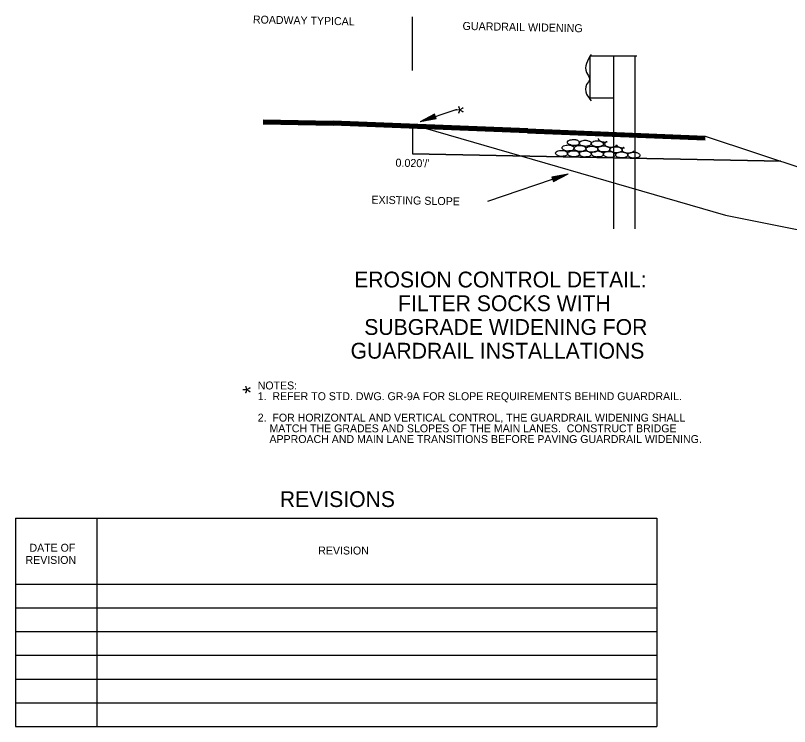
# Model space of a CAD drawing. Extents: x 1929624 to 1932070, y 596315 to 605533.
# Drawn here: x 1930529 to 1931116, y 604566 to 605106 of the extents above; entities that cross this region are included whole.
import ezdxf

# ---------------------------------------------------------------- set-up
doc = ezdxf.new("R2010")
doc.units = 0
for name, color, linetype in [('Default', 7, 'Continuous'), ('R_Border', 7, 'Continuous'), ('R_Logo', 7, 'Continuous')]:
    doc.layers.add(name, color=color, linetype=linetype)

msp = doc.modelspace()

# ---------------------------------------------------------------- linework, layer by layer
at = {"layer": 'Default'}
for p, q in [((1930964.98, 605075.01), (1930964.98, 605043.17)), ((1930964.98, 605075.01), (1931000.63, 605075.01)), ((1930982.82, 605075.01), (1930982.82, 604943.82)), ((1930999.21, 605074.86), (1930999.21, 604943.7)), ((1930964.98, 605043.17), (1930982.82, 605043.17)), ((1930863.17, 605034.12), (1930836.07, 605024.93)), ((1930847.11, 605030.72), (1930836.07, 605024.93)), ((1930848.31, 605027.26), (1930836.07, 605024.93)), ((1930847.23, 605030.43), (1930838, 605025.58)), ((1930848.23, 605027.52), (1930838, 605025.58)), ((1930847.34, 605030.1), (1930840.07, 605026.32)), ((1930848.09, 605027.84), (1930840.07, 605026.32)), ((1930847.39, 605029.82), (1930841.99, 605026.99)), ((1930847.99, 605028.14), (1930841.99, 605026.99)), ((1930847.51, 605029.56), (1930843.92, 605027.67)), ((1930847.88, 605028.46), (1930843.92, 605027.67)), ((1930847.61, 605029.26), (1930845.88, 605028.36)), ((1930847.83, 605028.76), (1930845.88, 605028.36)), ((1930848.31, 605027.26), (1930847.11, 605030.72)), ((1930717.07, 605026.44), (1930770.24, 605025.38)), ((1930717.07, 605025.7), (1930770.24, 605024.64)), ((1930717.1, 605024.96), (1930770.24, 605023.91)), ((1930717.12, 605024.23), (1930770.24, 605023.17)), ((1930717.15, 605023.49), (1930770.19, 605022.43)), ((1930717.15, 605023.39), (1930770.24, 605022.33)), ((1930917.77, 605016.53), (1930770.14, 605022.43)), ((1930917.82, 605018), (1930770.19, 605023.91)), ((1930917.82, 605017.26), (1930770.19, 605023.17)), ((1930917.87, 605019.48), (1930770.24, 605025.38)), ((1930917.87, 605018.74), (1930770.24, 605024.64)), ((1930917.77, 605016.43), (1930770.24, 605022.33)), ((1930830.34, 605022.98), (1930830.34, 605000.56)), ((1930917.74, 605016.53), (1931052.4, 605011.14)), ((1930917.77, 605017.26), (1931052.42, 605011.87)), ((1930917.8, 605018), (1931052.46, 605012.61)), ((1930917.82, 605018.74), (1931052.48, 605013.35)), ((1930917.87, 605019.48), (1931052.52, 605014.09)), ((1931052.52, 605014.09), (1931287.53, 604935.97)), ((1930887.54, 604964.72), (1930948.45, 604985.4)), ((1930936.22, 604983.06), (1930948.45, 604985.4)), ((1930936.22, 604983.06), (1930937.42, 604979.61)), ((1930936.3, 604982.8), (1930946.52, 604984.74)), ((1930936.44, 604982.48), (1930944.45, 604984)), ((1930936.53, 604982.18), (1930942.54, 604983.33)), ((1930936.65, 604981.87), (1930940.61, 604982.65)), ((1930936.69, 604981.57), (1930938.64, 604981.96)), ((1930936.92, 604981.07), (1930938.64, 604981.96)), ((1930937.01, 604980.76), (1930940.61, 604982.65)), ((1930937.14, 604980.5), (1930942.54, 604983.33)), ((1930937.19, 604980.23), (1930944.45, 604984)), ((1930937.29, 604979.89), (1930946.52, 604984.74)), ((1930937.42, 604979.61), (1930948.45, 604985.4))]:
    msp.add_line(p, q, dxfattribs=at)
for points in [[(1930965.84, 605076.04), (1930962.5, 605069.13), (1930962.32, 605062.39), (1930964.74, 605057.2), (1930962.5, 605053.26), (1930962.5, 605046), (1930966.04, 605040.76)], [(1930952.73, 605011.46), (1930951.11, 605011.37), (1930949.14, 605010.78), (1930948.1, 605009.84), (1930947.96, 605009.3), (1930948.45, 605008.32), (1930949.04, 605007.87), (1930950.17, 605007.33), (1930951.74, 605006.89), (1930952.58, 605006.89), (1930953.76, 605006.99), (1930955.09, 605007.13), (1930956.12, 605007.53), (1930957.01, 605008.36), (1930957.16, 605009), (1930956.86, 605009.89), (1930956.22, 605010.48), (1930955.53, 605010.87), (1930954.45, 605011.32), (1930953.76, 605011.46), (1930952.73, 605011.46)], [(1930961.55, 605010.94), (1930959.92, 605010.84), (1930958, 605010.15), (1930957.02, 605009.37), (1930956.87, 605008.82), (1930957.41, 605007.79), (1930957.85, 605007.25), (1930959.04, 605006.76), (1930960.51, 605006.41), (1930961.35, 605006.31), (1930962.58, 605006.36), (1930963.96, 605006.61), (1930964.94, 605007.05), (1930965.97, 605007.84), (1930966.12, 605008.48), (1930965.83, 605009.37), (1930965.09, 605010.01), (1930964.35, 605010.35), (1930963.27, 605010.69), (1930962.58, 605010.84), (1930961.55, 605010.94)], [(1930970.72, 605010.57), (1930969.1, 605010.52), (1930967.13, 605009.83), (1930966.15, 605008.95), (1930966, 605008.36), (1930966.54, 605007.37), (1930967.08, 605006.93), (1930968.16, 605006.44), (1930969.74, 605005.99), (1930970.58, 605005.95), (1930971.76, 605006.04), (1930973.08, 605006.29), (1930974.12, 605006.68), (1930975.1, 605007.47), (1930975.25, 605008.06), (1930974.95, 605008.95), (1930974.22, 605009.54), (1930973.53, 605010.03), (1930972.44, 605010.37), (1930971.76, 605010.52), (1930970.72, 605010.57)], [(1930971.34, 605012.16), (1930971.34, 605012.13), (1930971.34, 605012.06), (1930971.35, 605012), (1930971.42, 605011.73), (1930971.54, 605011.47), (1930971.69, 605011.21), (1930971.79, 605011.09), (1930971.89, 605010.96), (1930972.14, 605010.72), (1930972.43, 605010.52), (1930972.69, 605010.38), (1930972.96, 605010.25), (1930973.23, 605010.13), (1930973.51, 605010.03), (1930974.29, 605009.81), (1930975.09, 605009.64), (1930975.5, 605009.57), (1930975.71, 605009.55), (1930975.92, 605009.54), (1930976.51, 605009.57), (1930976.81, 605009.6), (1930977.1, 605009.64), (1930977.63, 605009.72), (1930978.14, 605009.82)], [(1930978, 605009.87), (1930977.7, 605009.75), (1930977.46, 605009.64), (1930977.22, 605009.51), (1930976.93, 605009.33), (1930976.67, 605009.12), (1930976.45, 605008.87), (1930976.34, 605008.73), (1930976.24, 605008.58), (1930976.16, 605008.44), (1930976.11, 605008.31), (1930976.08, 605008.17), (1930976.08, 605008.1), (1930976.09, 605008.04), (1930976.16, 605007.77), (1930976.28, 605007.5), (1930976.44, 605007.25), (1930976.53, 605007.12), (1930976.63, 605007), (1930976.89, 605006.75), (1930977.17, 605006.56), (1930977.44, 605006.42), (1930977.7, 605006.28), (1930977.97, 605006.17), (1930978.25, 605006.07), (1930979.03, 605005.85), (1930979.83, 605005.67), (1930980.66, 605005.58), (1930980.81, 605005.58), (1930980.96, 605005.58), (1930981.26, 605005.6), (1930981.85, 605005.67), (1930982.18, 605005.72), (1930982.51, 605005.78), (1930982.84, 605005.85), (1930983.17, 605005.92), (1930983.44, 605005.99), (1930983.7, 605006.09), (1930983.95, 605006.19), (1930984.21, 605006.31), (1930984.49, 605006.46), (1930984.74, 605006.63), (1930984.98, 605006.84), (1930985.09, 605006.96), (1930985.19, 605007.1), (1930985.26, 605007.22), (1930985.31, 605007.34)], [(1930943.63, 605003.26), (1930942.01, 605003.21), (1930940.04, 605002.53), (1930939.11, 605001.64), (1930938.96, 605001.05), (1930939.45, 605000.07), (1930940.04, 604999.62), (1930941.08, 604999.13), (1930942.7, 604998.69), (1930943.49, 604998.64), (1930944.72, 604998.74), (1930946.05, 604998.98), (1930947.08, 604999.38), (1930948.01, 605000.16), (1930948.16, 605000.75), (1930947.87, 605001.64), (1930947.13, 605002.23), (1930946.44, 605002.72), (1930945.36, 605003.07), (1930944.67, 605003.21), (1930943.63, 605003.26)], [(1930948.65, 605007.36), (1930946.93, 605007.16), (1930945.01, 605006.67), (1930944.03, 605005.73), (1930943.88, 605005.19), (1930944.37, 605004.16), (1930944.96, 605003.71), (1930946.05, 605003.12), (1930947.62, 605002.73), (1930948.41, 605002.73), (1930949.64, 605002.83), (1930951.02, 605002.93), (1930952.05, 605003.42), (1930952.93, 605004.26), (1930953.08, 605004.9), (1930952.79, 605005.78), (1930952.05, 605006.37), (1930951.36, 605006.67), (1930950.28, 605007.11), (1930949.64, 605007.31), (1930948.65, 605007.36)], [(1930957.58, 605006.94), (1930955.96, 605006.89), (1930953.99, 605006.25), (1930953.01, 605005.31), (1930952.86, 605004.77), (1930953.4, 605003.74), (1930953.94, 605003.3), (1930955.03, 605002.8), (1930956.6, 605002.41), (1930957.44, 605002.31), (1930958.62, 605002.41), (1930959.95, 605002.66), (1930960.98, 605003.05), (1930961.96, 605003.84), (1930962.11, 605004.48), (1930961.82, 605005.36), (1930961.08, 605005.95), (1930960.39, 605006.4), (1930959.31, 605006.74), (1930958.62, 605006.89), (1930957.58, 605006.94)], [(1930966.68, 605006.44), (1930965.06, 605006.29), (1930963.09, 605005.75), (1930962.05, 605004.81), (1930961.91, 605004.27), (1930962.45, 605003.29), (1930962.99, 605002.85), (1930964.12, 605002.21), (1930965.65, 605001.86), (1930966.48, 605001.86), (1930967.66, 605001.96), (1930969.09, 605002.01), (1930970.07, 605002.5), (1930971.01, 605003.34), (1930971.16, 605003.98), (1930970.86, 605004.86), (1930970.17, 605005.45), (1930969.44, 605005.8), (1930968.4, 605006.14), (1930967.71, 605006.44), (1930966.68, 605006.44)], [(1930975.64, 605006.67), (1930974.01, 605006.47), (1930972.09, 605005.98), (1930971.11, 605005.04), (1930970.96, 605004.5), (1930971.5, 605003.47), (1930972.04, 605003.03), (1930973.13, 605002.44), (1930974.7, 605002.04), (1930975.49, 605002.04), (1930976.72, 605002.14), (1930978.05, 605002.24), (1930979.13, 605002.73), (1930980.06, 605003.57), (1930980.21, 605004.21), (1930979.92, 605005.09), (1930979.18, 605005.68), (1930978.44, 605005.98), (1930977.41, 605006.47), (1930976.67, 605006.62), (1930975.64, 605006.67)], [(1930984.94, 605006.03), (1930983.31, 605005.98), (1930981.34, 605005.34), (1930980.36, 605004.4), (1930980.21, 605003.86), (1930980.75, 605002.83), (1930981.29, 605002.39), (1930982.38, 605001.89), (1930983.95, 605001.5), (1930984.79, 605001.4), (1930985.97, 605001.5), (1930987.3, 605001.75), (1930988.33, 605002.14), (1930989.31, 605002.93), (1930989.46, 605003.57), (1930989.17, 605004.45), (1930988.43, 605005.04), (1930987.74, 605005.49), (1930986.66, 605005.83), (1930985.97, 605005.98), (1930984.94, 605006.03)], [(1930985.26, 605007.36), (1930985.34, 605007.16), (1930985.45, 605006.96), (1930985.58, 605006.76), (1930985.73, 605006.58), (1930985.99, 605006.33), (1930986.27, 605006.13), (1930986.54, 605005.99), (1930986.8, 605005.86), (1930987.07, 605005.74), (1930987.36, 605005.64), (1930988.14, 605005.42), (1930988.93, 605005.25), (1930989.35, 605005.18), (1930989.56, 605005.16), (1930989.77, 605005.15), (1930990.36, 605005.18), (1930990.95, 605005.25), (1930991.25, 605005.29)], [(1930990.83, 605005.44), (1930990.57, 605005.32), (1930990.44, 605005.25), (1930990.31, 605005.18), (1930990.01, 605005), (1930989.76, 605004.78), (1930989.53, 605004.54), (1930989.43, 605004.4), (1930989.32, 605004.25), (1930989.25, 605004.11), (1930989.19, 605003.98), (1930989.17, 605003.84), (1930989.17, 605003.77), (1930989.17, 605003.71), (1930989.25, 605003.44), (1930989.36, 605003.17), (1930989.52, 605002.92), (1930989.61, 605002.79), (1930989.72, 605002.67), (1930989.97, 605002.42), (1930990.26, 605002.23), (1930990.52, 605002.08), (1930990.79, 605001.95), (1930991.06, 605001.84), (1930991.34, 605001.74), (1930992.12, 605001.52), (1930992.91, 605001.34), (1930993.75, 605001.24), (1930993.9, 605001.25), (1930994.05, 605001.25), (1930994.34, 605001.27), (1930994.93, 605001.34), (1930995.27, 605001.39), (1930995.6, 605001.45), (1930995.93, 605001.52), (1930996.26, 605001.59), (1930996.53, 605001.66), (1930996.79, 605001.76), (1930997.04, 605001.86), (1930997.29, 605001.98), (1930997.57, 605002.13), (1930997.83, 605002.3), (1930998.06, 605002.51), (1930998.17, 605002.63), (1930998.23, 605002.7), (1930998.28, 605002.77), (1930998.33, 605002.85)], [(1930952.74, 605002.98), (1930951.11, 605002.83), (1930949.15, 605002.24), (1930948.21, 605001.35), (1930948.06, 605000.76), (1930948.55, 604999.78), (1930949.05, 604999.34), (1930950.18, 604998.84), (1930951.7, 604998.35), (1930952.54, 604998.35), (1930953.77, 604998.45), (1930955.15, 604998.65), (1930956.13, 604998.99), (1930957.12, 604999.88), (1930957.26, 605000.47), (1930956.97, 605001.35), (1930956.23, 605001.94), (1930955.49, 605002.39), (1930954.46, 605002.78), (1930953.77, 605002.93), (1930952.74, 605002.98)], [(1930961.59, 605002.85), (1930959.96, 605002.65), (1930957.99, 605002.11), (1930957.01, 605001.22), (1930956.86, 605000.63), (1930957.4, 604999.65), (1930957.95, 604999.2), (1930959.03, 604998.61), (1930960.55, 604998.22), (1930961.39, 604998.22), (1930962.62, 604998.32), (1930963.95, 604998.42), (1930964.98, 604998.86), (1930965.97, 604999.75), (1930966.11, 605000.34), (1930965.82, 605001.22), (1930965.08, 605001.81), (1930964.34, 605002.16), (1930963.26, 605002.55), (1930962.62, 605002.8), (1930961.59, 605002.85)], [(1930970.85, 605002.85), (1930969.17, 605002.66), (1930967.2, 605002.12), (1930966.22, 605001.23), (1930966.07, 605000.64), (1930966.61, 604999.66), (1930967.16, 604999.21), (1930968.29, 604998.57), (1930969.81, 604998.23), (1930970.6, 604998.23), (1930971.83, 604998.28), (1930973.21, 604998.42), (1930974.24, 604998.87), (1930975.18, 604999.75), (1930975.32, 605000.34), (1930975.03, 605001.23), (1930974.29, 605001.82), (1930973.55, 605002.16), (1930972.52, 605002.51), (1930971.88, 605002.71), (1930970.85, 605002.85)], [(1930979.92, 605002.48), (1930978.19, 605002.29), (1930976.32, 605001.8), (1930975.29, 605000.86), (1930975.14, 605000.32), (1930975.68, 604999.29), (1930976.23, 604998.84), (1930977.36, 604998.25), (1930978.88, 604997.86), (1930979.67, 604997.86), (1930980.9, 604997.96), (1930982.33, 604998.06), (1930983.31, 604998.55), (1930984.25, 604999.38), (1930984.39, 605000.02), (1930984.1, 605000.91), (1930983.36, 605001.5), (1930982.67, 605001.8), (1930981.59, 605002.19), (1930980.95, 605002.44), (1930979.92, 605002.48)], [(1930989.19, 605002.11), (1930987.57, 605002.01), (1930985.65, 605001.32), (1930984.66, 605000.53), (1930984.52, 604999.99), (1930985.06, 604998.96), (1930985.5, 604998.42), (1930986.68, 604997.92), (1930988.16, 604997.58), (1930989, 604997.48), (1930990.23, 604997.53), (1930991.6, 604997.78), (1930992.59, 604998.22), (1930993.62, 604999.01), (1930993.77, 604999.65), (1930993.47, 605000.53), (1930992.73, 605001.17), (1930992, 605001.52), (1930990.91, 605001.86), (1930990.23, 605002.01), (1930989.19, 605002.11)], [(1930998.44, 605001.92), (1930996.82, 605001.77), (1930994.85, 605001.18), (1930993.92, 605000.29), (1930993.77, 604999.7), (1930994.26, 604998.72), (1930994.75, 604998.28), (1930995.88, 604997.79), (1930997.41, 604997.29), (1930998.25, 604997.29), (1930999.48, 604997.39), (1931000.85, 604997.59), (1931001.84, 604997.93), (1931002.82, 604998.82), (1931002.97, 604999.41), (1931002.67, 605000.29), (1931001.94, 605000.89), (1931001.2, 605001.33), (1931000.17, 605001.72), (1930999.48, 605001.87), (1930998.44, 605001.92)]]:
    msp.add_spline(points, degree=3, dxfattribs=at)
at = {"layer": 'R_Border'}
for p, q in [((1930830.34, 605063.76), (1930830.34, 605104.53)), ((1930830.3, 605000.56), (1931109.97, 604995)), ((1931109.97, 604995), (1930830.3, 605000.56)), ((1930830.34, 605000.56), (1930830.3, 605000.56))]:
    msp.add_line(p, q, dxfattribs=at)
msp.add_lwpolyline([(1930830.34, 605022.98), (1931067.88, 604954.04), (1931172.78, 604933.18), (1931225.62, 604931.58), (1931273.23, 604935.95), (1931377.44, 604935.97)], dxfattribs=at)
at = {"layer": 'R_Logo'}
for p, q in [((1930529.08, 604724.22), (1931015.76, 604724.22)), ((1930529.08, 604724.22), (1930529.08, 604566.26)), ((1930590.87, 604724.22), (1930590.87, 604566.26)), ((1931015.76, 604724.22), (1931015.76, 604566.26)), ((1930529.08, 604674.23), (1931015.76, 604674.23)), ((1930529.08, 604656.24), (1931015.76, 604656.24)), ((1930529.08, 604638.24), (1931015.76, 604638.24)), ((1930529.08, 604620.25), (1931015.76, 604620.25)), ((1930529.08, 604602.25), (1931015.76, 604602.25)), ((1930529.08, 604584.25), (1931015.76, 604584.25)), ((1930529.08, 604566.26), (1931015.76, 604566.26))]:
    msp.add_line(p, q, dxfattribs=at)

# ---------------------------------------------------------------- texts
at = {"layer": 'Default'}
for s, height, rotation, p in [('ROADWAY TYPICAL', 6, 358.8537, (1930709.26, 605099.57)), ('GUARDRAIL WIDENING', 6.075, 358.8537, (1930868.31, 605094.64)), ('*', 12, 90, (1930875.18, 605030.87)), ("0.020'/'", 6.075, 358.8537, (1930817.43, 604990.89)), ('EXISTING SLOPE', 6.075, 358.8537, (1930799.1, 604962.85)), ('EROSION CONTROL DETAIL:', 12, 360, (1930786.11, 604899.28)), ('FILTER SOCKS WITH', 12, 360, (1930819.44, 604881.28)), (' SUBGRADE WIDENING FOR', 12, 360, (1930789.3, 604863.28)), ('GUARDRAIL INSTALLATIONS', 12, 360, (1930783.41, 604845.28)), ('*', 12, 90, (1930713.56, 604818.57))]:
    msp.add_text(s, height=height, rotation=rotation, dxfattribs=at).set_placement(p)
for s, p in [('NOTES:', (1930712.92, 604821.92)), ('1.  REFER TO STD. DWG. GR-9A FOR SLOPE REQUIREMENTS BEHIND GUARDRAIL.', (1930712.92, 604813.79)), ('2.  FOR HORIZONTAL AND VERTICAL CONTROL, THE GUARDRAIL WIDENING SHALL', (1930712.92, 604797.54)), ('    MATCH THE GRADES AND SLOPES OF THE MAIN LANES.  CONSTRUCT BRIDGE', (1930712.92, 604789.41)), ('    APPROACH AND MAIN LANE TRANSITIONS BEFORE PAVING GUARDRAIL WIDENING.', (1930712.92, 604781.28))]:
    msp.add_text(s, height=6, dxfattribs=at).set_placement(p)
at = {"layer": 'R_Logo'}
for s, height, p in [('REVISIONS', 11.997, (1930729.68, 604732.72)), ('DATE OF', 5.998, (1930539.71, 604698.85)), ('REVISION', 5.998, (1930758.88, 604696.73)), ('REVISION', 5.998, (1930536.72, 604689.6))]:
    msp.add_text(s, height=height, dxfattribs=at).set_placement(p)

doc.saveas('drawing.dxf')
